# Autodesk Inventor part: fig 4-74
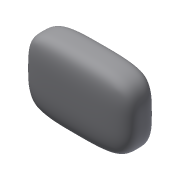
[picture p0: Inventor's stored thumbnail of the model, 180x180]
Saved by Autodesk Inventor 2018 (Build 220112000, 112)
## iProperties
Created: 2012-07
Part Number: fig 4-74
Material: Generic
Document SubType Name: Modeling
Designer: CADCIM
Density: 1 g/cm^3
Appearance: Default
Author: CADCIM
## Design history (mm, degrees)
feature "Form1"
body "Solid1"
body "Solid2"
